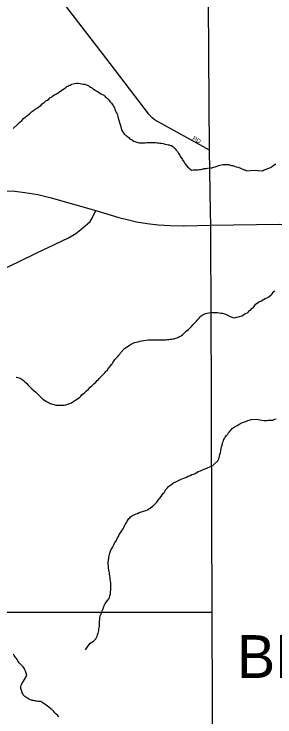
# Model space of a CAD drawing. Extents: x 2010165 to 2382125, y 1060529 to 1407316.
# Drawn here: x 2206176 to 2209222, y 1204883 to 1213095 of the extents above; entities that cross this region are included whole.
import ezdxf

# ---------------------------------------------------------------- set-up
doc = ezdxf.new("R2010")
doc.units = 0
for name, color, linetype in [('GM_X_City_Street', 7, 'Continuous'), ('GM_X_City_Street_Text', 7, 'Continuous'), ('GM_X_Corporation_Text', 7, 'Continuous'), ('GM_X_Minor_River', 7, 'Continuous'), ('GM_X_State_Route', 7, 'Continuous')]:
    doc.layers.add(name, color=color, linetype=linetype)

msp = doc.modelspace()

# ---------------------------------------------------------------- linework, layer by layer
at = {"layer": 'GM_X_City_Street'}
for points in [[(2208456.6, 1211503.7), (2207822.4, 1211855.1), (2207786.6, 1211884.3), (2207748.6, 1211924.5), (2207247.8, 1212584.4), (2206408.8, 1213676.7), (2206379.3, 1213700.3), (2206352.7, 1213718), (2205831, 1213951.2), (2204601.3, 1214502.8), (2204508.6, 1214550.1), (2204421.7, 1214605.1), (2204416.3, 1214608.5)], [(2206573.3, 1210367.5), (2206810.5, 1210481.5), (2206895.8, 1210533.1), (2206975.2, 1210594.6), (2207064.6, 1210672), (2207086.4, 1210709.7), (2207130.1, 1210801)], [(2204477.5, 1203768.7), (2204517.1, 1203815.6), (2205378, 1204812.6), (2205560.9, 1205022), (2205621, 1205118.3), (2205657.1, 1205237.2), (2205848.8, 1206107.4), (2205913.8, 1206390.7), (2205926.1, 1206514.8), (2205923.3, 1206613), (2205534.4, 1208354.5), (2205455.5, 1208700.4), (2205414.2, 1208898.4), (2205410.7, 1208963.9), (2205440, 1209055.1), (2205701.7, 1209548.4), (2205904.8, 1209922.1), (2205958.6, 1210019.5), (2206002.3, 1210073.5), (2206063.1, 1210121.7), (2206236.8, 1210203.6), (2206451.2, 1210308.8), (2206573.3, 1210367.5)], [(2196693.1, 1206074.3), (2200608.2, 1206079.6), (2202550.7, 1206093.1), (2205848.8, 1206107.4), (2208487.9, 1206109.2)]]:
    msp.add_lwpolyline(points, dxfattribs=at)
at = {"layer": 'GM_X_Minor_River'}
for points in [[(2206611.9, 1212125.5), (2206629.6, 1212138), (2206649.3, 1212150.6), (2206671, 1212163.2), (2206690.7, 1212175.8), (2206712.4, 1212190.4), (2206741.9, 1212211.2), (2206757.7, 1212221.7), (2206769.5, 1212230), (2206781.3, 1212238.4), (2206793.1, 1212246.7), (2206804.9, 1212253), (2206816.8, 1212259.4), (2206830.7, 1212265.8), (2206842.6, 1212270.1), (2206852.5, 1212274.3), (2206866.4, 1212278.7), (2206882.3, 1212283.2), (2206906.3, 1212285.8), (2206926.4, 1212286.3), (2206946.5, 1212282.8), (2206964.6, 1212281.3), (2206982.7, 1212277.8), (2207000.9, 1212274.2), (2207019.1, 1212268.7), (2207035.3, 1212263.1), (2207047.5, 1212255.4), (2207057.8, 1212247.6), (2207070, 1212239.9), (2207090.4, 1212228.4), (2207104.7, 1212216.7), (2207169.9, 1212178.3), (2207188.3, 1212164.7), (2207206.6, 1212155.2), (2207218.8, 1212149.4), (2207231.2, 1212137.7), (2207245.6, 1212122), (2207261.9, 1212112.4), (2207274.3, 1212100.7), (2207286.7, 1212087), (2207299.2, 1212069.2), (2207313.6, 1212055.6), (2207321.9, 1212043.7), (2207330.3, 1212031.9), (2207336.6, 1212022), (2207342.8, 1212012.2), (2207347.2, 1211998.2), (2207353.7, 1211982.3), (2207362.2, 1211964.5), (2207368.6, 1211950.6), (2207372.9, 1211938.7), (2207379.2, 1211928.8), (2207383.6, 1211914.9), (2207388, 1211898.9), (2207392.6, 1211876.9), (2207399.2, 1211855), (2207405.9, 1211829.1), (2207414.7, 1211803.2), (2207421.4, 1211777.3), (2207430.3, 1211743.4), (2207440.9, 1211723.6), (2207449.3, 1211709.8), (2207459.6, 1211698), (2207465.9, 1211688.1), (2207480.2, 1211678.5), (2207494.5, 1211668.8), (2207515, 1211651.3), (2207525.3, 1211641.5), (2207535.5, 1211633.8), (2207545.7, 1211628), (2207555.9, 1211622.2), (2207574.3, 1211610.7), (2207620.8, 1211595.8), (2207634.9, 1211592.2), (2207655, 1211590.7), (2207665, 1211591), (2207677.1, 1211591.3), (2207697.1, 1211591.8), (2207707.1, 1211592.1), (2207725.1, 1211594.6), (2207749.1, 1211595.2), (2207769.2, 1211595.7), (2207785.3, 1211594.1), (2207803.3, 1211594.6), (2207827.4, 1211593.2), (2207845.5, 1211591.7), (2207863.6, 1211590.2), (2207879.7, 1211586.6), (2207897.8, 1211585.1), (2207918, 1211581.6), (2207940.2, 1211576.1), (2207960.4, 1211570.6), (2207976.5, 1211567), (2207988.6, 1211565.3), (2208000.8, 1211559.6), (2208012.8, 1211557.9), (2208029.1, 1211548.3), (2208045.6, 1211532.7), (2208056, 1211520.9), (2208070.4, 1211505.3), (2208082.9, 1211487.5)], [(2206166.6, 1211756.4), (2206221.3, 1211810.1), (2206240.9, 1211826.6), (2206266.3, 1211851.4), (2206287.8, 1211874.1), (2206311.3, 1211892.8), (2206334.9, 1211911.4), (2206356.5, 1211930.1), (2206380, 1211950.8), (2206401.6, 1211967.4), (2206423.2, 1211984), (2206448.9, 1211998.8), (2206468.5, 1212013.3), (2206488.2, 1212027.9), (2206505.7, 1212046.4), (2206529.3, 1212063.1), (2206546.9, 1212079.6), (2206564.7, 1212090.1), (2206580.4, 1212102.6), (2206594.1, 1212115), (2206611.9, 1212125.5)], [(2208082.9, 1211487.5), (2208095.6, 1211465.8), (2208110.1, 1211446.1), (2208120.6, 1211428.3), (2208133.2, 1211406.5), (2208141.6, 1211394.7), (2208147.9, 1211382.8), (2208160.5, 1211363.1), (2208170.9, 1211347.3), (2208185.5, 1211329.6), (2208202, 1211309.9), (2208218.5, 1211294.3), (2208232.8, 1211282.7), (2208249.1, 1211273.1), (2208267.2, 1211273.5), (2208287.2, 1211274), (2208307.2, 1211276.6), (2208323.2, 1211277), (2208339.3, 1211277.4), (2208353.2, 1211279.8), (2208367.2, 1211282.2), (2208377.2, 1211284.4), (2208393.1, 1211288.9), (2208407.1, 1211291.2), (2208417.1, 1211291.5), (2208435.1, 1211294), (2208453, 1211296.5), (2208471.1, 1211296.9), (2208485.1, 1211299.3), (2208497, 1211301.6), (2208508.9, 1211306), (2208524.9, 1211310.4), (2208536.8, 1211314.7), (2208546.7, 1211319), (2208562.6, 1211325.4), (2208576.5, 1211329.8), (2208596.4, 1211334.3), (2208612.4, 1211336.8), (2208628.4, 1211337.2), (2208646.5, 1211337.7), (2208668.5, 1211338.3), (2208682.6, 1211336.6), (2208700.8, 1211331.1), (2208714.9, 1211327.4), (2208731, 1211323.8), (2208749.2, 1211318.3), (2208769.5, 1211310.8), (2208791.7, 1211305.3), (2208810, 1211297.8), (2208828.2, 1211290.2), (2208846.5, 1211282.7), (2208860.6, 1211277), (2208870.8, 1211273.3), (2208895.1, 1211261.9), (2208974.2, 1211269.9)], [(2208974.2, 1211271.2), (2209075.2, 1211261.8), (2209089.1, 1211272), (2209150.9, 1211294.9), (2209170.8, 1211303.1), (2209192.7, 1211317.5), (2209214.5, 1211331.8), (2209230.4, 1211346.1)], [(2209221.8, 1209862.3), (2209207.9, 1209850.1), (2209194.1, 1209837.9), (2209186.2, 1209827.8), (2209176.4, 1209811.6), (2209164.4, 1209805.4), (2209152.6, 1209793.2), (2209140.7, 1209785), (2209108.8, 1209768.5), (2209088.9, 1209758.2), (2209079, 1209752.1), (2209069, 1209745.9), (2209055.1, 1209737.7), (2209043.2, 1209731.6), (2209031.3, 1209723.4), (2209029.3, 1209723.3), (2208989.5, 1209699.6)], [(2208079.5, 1209313.2), (2208095.4, 1209319.7), (2208109.3, 1209326.1), (2208125.1, 1209334.5), (2208140.8, 1209347), (2208160.3, 1209365.5), (2208185.7, 1209390.3), (2208213.3, 1209411.1), (2208230.9, 1209427.6), (2208246.4, 1209444.1), (2208267.9, 1209466.7), (2208279.5, 1209481.1), (2208293.2, 1209493.5), (2208304.9, 1209505.8), (2208314.6, 1209518.1), (2208326.3, 1209530.5), (2208338, 1209542.8), (2208349.7, 1209557.2), (2208361.4, 1209567.6), (2208371.2, 1209577.8), (2208412.8, 1209595), (2208430.7, 1209599.5), (2208448.7, 1209604), (2208468.7, 1209606.5), (2208486.7, 1209607), (2208504.7, 1209607.4), (2208526.8, 1209608), (2208548.9, 1209606.6), (2208569, 1209605.1), (2208589.1, 1209601.6), (2208609.2, 1209600.1), (2208631.5, 1209592.7), (2208645.6, 1209587.1), (2208659.9, 1209579.4), (2208682.2, 1209569.9), (2208706.6, 1209556.5), (2208730.8, 1209551.1), (2208751, 1209547.7), (2208774.9, 1209552.3), (2208806.8, 1209561.2), (2208834.6, 1209569.9), (2208856.4, 1209580.6), (2208876, 1209595.1), (2208899.8, 1209605.8), (2208913.6, 1209616.2), (2208925.2, 1209630.5), (2208935.1, 1209636.8), (2208950.7, 1209653.3), (2208966.4, 1209663.7), (2208989.5, 1209699.6)], [(2206199, 1208854.3), (2206205, 1208852.5), (2206219.2, 1208848.8), (2206235.4, 1208843.2), (2206251.6, 1208835.7), (2206265.9, 1208828), (2206286.3, 1208814.5), (2206302.7, 1208798.8), (2206321.3, 1208781.3), (2206341.9, 1208759.7), (2206364.6, 1208736.2), (2206385.2, 1208714.7), (2206407.8, 1208695.2), (2206428.4, 1208675.7), (2206448.9, 1208658.1), (2206467.5, 1208638.6), (2206490.1, 1208619.1), (2206512.8, 1208595.6), (2206543.4, 1208576.3), (2206563.8, 1208562.8), (2206584.1, 1208553.3), (2206598.4, 1208545.6), (2206612.5, 1208542), (2206626.7, 1208536.3), (2206644.8, 1208532.8), (2206663, 1208527.3), (2206683.2, 1208523.8), (2206761.3, 1208525.8), (2206781.3, 1208530.4), (2206805.1, 1208537), (2206827, 1208545.6), (2206844.8, 1208554.1), (2206862.5, 1208564.6), (2206884.2, 1208579.2), (2206927.6, 1208606.5), (2206943.3, 1208618.9), (2206957, 1208629.3), (2206972.5, 1208649.8), (2206998.1, 1208668.6), (2207021.5, 1208693.2), (2207045, 1208713.9), (2207066.5, 1208734.6), (2207086, 1208753.2), (2207107.5, 1208773.8), (2207129, 1208794.4), (2207146.6, 1208813), (2207162.2, 1208827.4), (2207173.9, 1208841.8), (2207183.6, 1208854.1), (2207193.4, 1208862.4), (2207207, 1208876.8), (2207218.7, 1208889.1), (2207234.4, 1208903.6), (2207248, 1208918), (2207255.8, 1208928.3), (2207265.6, 1208936.5), (2207271.3, 1208946.7), (2207282.9, 1208963.1), (2207294.6, 1208975.4), (2207304.3, 1208987.7), (2207312, 1209000), (2207319.7, 1209010.2), (2207329.4, 1209022.5), (2207341, 1209038.9), (2207354.5, 1209057.3), (2207370.1, 1209075.8), (2207387.6, 1209094.3), (2207399.2, 1209110.7), (2207410.9, 1209123), (2207420.6, 1209135.3), (2207465.3, 1209186.7), (2207486.9, 1209203.3), (2207506.7, 1209215.9), (2207522.4, 1209226.3), (2207536.2, 1209234.7), (2207550, 1209243.1), (2207567.9, 1209249.6), (2207583.8, 1209256.1), (2207601.7, 1209262.5), (2207625.6, 1209267.2), (2207643.5, 1209271.7), (2207665.5, 1209276.3), (2207691.4, 1209281), (2207717.4, 1209283.6), (2207741.3, 1209288.3), (2207767.4, 1209289), (2207795.4, 1209289.7), (2207831.6, 1209288.6), (2207857.6, 1209289.3), (2207881.7, 1209288), (2207903.7, 1209288.5), (2207925.8, 1209289.1), (2207947.8, 1209289.7), (2207967.8, 1209292.2), (2207983.8, 1209292.6), (2207999.8, 1209295.1), (2208013.8, 1209295.4), (2208029.8, 1209299.9), (2208043.7, 1209302.2), (2208063.7, 1209306.8), (2208079.5, 1209313.2)], [(2207788, 1207340.3), (2207807.6, 1207356.8), (2207825.2, 1207373.4), (2207842.7, 1207393.9), (2207860.2, 1207414.4), (2207877.6, 1207439), (2207893.1, 1207457.4), (2207906.6, 1207477.9), (2207920.2, 1207496.3), (2207933.8, 1207510.7), (2207941.4, 1207525), (2207949, 1207541.2), (2207960.8, 1207551.6), (2207968.5, 1207561.8), (2207978.2, 1207574.1), (2207995.9, 1207588.6), (2208005.7, 1207596.9), (2208021.5, 1207605.4), (2208039.1, 1207619.9), (2208062.9, 1207630.5), (2208086.6, 1207643.2), (2208112.4, 1207653.9), (2208128.3, 1207660.4), (2208148.1, 1207668.9), (2208167.9, 1207677.4), (2208187.7, 1207686), (2208209.6, 1207694.6), (2208231.4, 1207703.2), (2208253.2, 1207713.8), (2208275, 1207720.4), (2208290.9, 1207728.9), (2208308.7, 1207737.3), (2208326.4, 1207749.9), (2208352.2, 1207758.6), (2208368, 1207767), (2208385.9, 1207773.5), (2208413.6, 1207786.3), (2208427.6, 1207790.7), (2208443.4, 1207797.1), (2208461.2, 1207805.6), (2208481.1, 1207814.1), (2208496.9, 1207822.6), (2208512.6, 1207835.1), (2208553.6, 1207874.3), (2208559.4, 1207884.5), (2208565, 1207898.7), (2208570.6, 1207912.9), (2208576.2, 1207929.1), (2208579.7, 1207949.2), (2208585.1, 1207969.4), (2208588.5, 1207991.6), (2208594, 1208013.8), (2208597.3, 1208040), (2208604.7, 1208060.3), (2208608.3, 1208076.4), (2208613.9, 1208092.7), (2208619.5, 1208108.9), (2208625.1, 1208123.1), (2208632.7, 1208137.3), (2208642.4, 1208151.6), (2208657.9, 1208172.1), (2208667.6, 1208184.4), (2208677.2, 1208196.7), (2208690.8, 1208215.1), (2208700.5, 1208225.4), (2208710.2, 1208237.7), (2208723.9, 1208252.1), (2208735.7, 1208260.5), (2208759.3, 1208277.1), (2208779.1, 1208287.7), (2208800.8, 1208300.3), (2208824.4, 1208315), (2208854.2, 1208325.8), (2208870.1, 1208332.2), (2208880, 1208336.5), (2208895.9, 1208343), (2208905.8, 1208347.2), (2208919.7, 1208351.6), (2208933.6, 1208356), (2208943.6, 1208358.3), (2209002.6, 1208363.9)], [(2209002.6, 1208363.9), (2209091.4, 1208345), (2209109.5, 1208345.2), (2209127.5, 1208347.4), (2209141.5, 1208349.6), (2209159.5, 1208349.8), (2209195.5, 1208352.3), (2209219.5, 1208360.6), (2209237.4, 1208366.9)], [(2207009.2, 1205665.6), (2207032.2, 1205702.4), (2207065.1, 1205745.4), (2207102.6, 1205768.5), (2207120.3, 1205783), (2207130, 1205795.3), (2207137.6, 1205809.5), (2207145.2, 1205825.8), (2207150.7, 1205844), (2207158.2, 1205862.3), (2207161.8, 1205878.4), (2207165.4, 1205894.6), (2207167, 1205908.7), (2207170.6, 1205924.8), (2207172, 1205944.9), (2207173.6, 1205961.1), (2207173.2, 1205977.1), (2207172.9, 1205989.1), (2207174.5, 1206003.2), (2207176, 1206021.3), (2207177.5, 1206041.4), (2207182.9, 1206063.7), (2207192.3, 1206086), (2207199.8, 1206106.3), (2207205.3, 1206122.5), (2207211, 1206136.7), (2207214.7, 1206148.8), (2207220.3, 1206163), (2207227.8, 1206183.3), (2207241.1, 1206207.7), (2207256.6, 1206228.2), (2207270.2, 1206246.6), (2207281.7, 1206265), (2207289.3, 1206279.3), (2207294.9, 1206297.5), (2207300.3, 1206319.7), (2207303.6, 1206343.9), (2207305, 1206366), (2207304.4, 1206388.1), (2207305.7, 1206416.2), (2207304.9, 1206446.3), (2207302.1, 1206474.3), (2207299.7, 1206490.3), (2207297.1, 1206510.3), (2207294.6, 1206530.3), (2207292, 1206550.3), (2207289.5, 1206568.3), (2207287.1, 1206582.3), (2207280.1, 1206620.3), (2207277.8, 1206632.3), (2207277.4, 1206648.3), (2207274.9, 1206664.3), (2207274.5, 1206680.4), (2207276, 1206698.5), (2207277.7, 1206710.6), (2207277.3, 1206722.6), (2207281, 1206734.8), (2207282.7, 1206746.8), (2207286.2, 1206767), (2207289.8, 1206779.1), (2207293.4, 1206795.3), (2207297.1, 1206807.4), (2207300.8, 1206819.6), (2207306.5, 1206831.8), (2207310.2, 1206841.9), (2207316, 1206852.1), (2207323.6, 1206864.3), (2207331.3, 1206878.6), (2207340.9, 1206892.9), (2207348.4, 1206913.2), (2207360, 1206927.5), (2207367.7, 1206941.8), (2207375.2, 1206958.1), (2207384.8, 1206974.4), (2207394.4, 1206992.7), (2207403.8, 1207013), (2207417.3, 1207033.4), (2207430.8, 1207053.9), (2207442.4, 1207070.2), (2207450.1, 1207080.5), (2207457.8, 1207094.7), (2207467.3, 1207115), (2207474.8, 1207131.3), (2207484.4, 1207147.6), (2207492.1, 1207159.9), (2207497.8, 1207170.1), (2207503.5, 1207182.2), (2207517, 1207202.7), (2207526.8, 1207210.9), (2207536.6, 1207219.2), (2207558.2, 1207237.9), (2207574, 1207244.3), (2207586, 1207248.6), (2207599.8, 1207255), (2207615.7, 1207261.5), (2207637.5, 1207270.1), (2207713, 1207296.1), (2207732.8, 1207304.7), (2207748.6, 1207313.1), (2207764.4, 1207323.6), (2207788, 1207340.3)], [(2206699.4, 1204882.6), (2206684.9, 1204902.3), (2206664.4, 1204917.8), (2206652, 1204931.5), (2206639.5, 1204947.3), (2206629.2, 1204959), (2206618.9, 1204968.8), (2206606.7, 1204976.5), (2206596.4, 1204986.3), (2206582, 1204997.9), (2206567.7, 1205009.6), (2206551.4, 1205019.2), (2206535, 1205030.8), (2206516.7, 1205042.4), (2206502.3, 1205054.1), (2206488, 1205063.7), (2206478, 1205063.5), (2206465.9, 1205065.2), (2206455.9, 1205064.9), (2206441.8, 1205066.6), (2206429.7, 1205068.2), (2206417.6, 1205071.9), (2206401.5, 1205075.5), (2206389.4, 1205077.2), (2206379.3, 1205081), (2206369.1, 1205084.7), (2206359, 1205088.4), (2206348.9, 1205092.2), (2206338.6, 1205100), (2206326.4, 1205107.7), (2206314.2, 1205115.4), (2206301.9, 1205123.1), (2206283.3, 1205142.7), (2206277.1, 1205152.6), (2206272.7, 1205164.5), (2206266.2, 1205184.4), (2206259.7, 1205202.3), (2206255.3, 1205216.2), (2206255, 1205226.3), (2206256.6, 1205240.3), (2206260.3, 1205254.5), (2206265.9, 1205268.7), (2206298.5, 1205321.8), (2206304.2, 1205333.9), (2206310, 1205344.1), (2206317.7, 1205354.4), (2206323.4, 1205366.6), (2206321.1, 1205378.6), (2206320.8, 1205388.6), (2206314.4, 1205404.5), (2206310, 1205418.4), (2206303.6, 1205432.3), (2206297.2, 1205446.2), (2206290.9, 1205458.1), (2206282.6, 1205467.9), (2206270.2, 1205481.6), (2206257.9, 1205491.3), (2206245.5, 1205505.1), (2206235.1, 1205516.8), (2206228.8, 1205526.7), (2206220.4, 1205540.5), (2206212.1, 1205552.4), (2206203.8, 1205564.2), (2206197.5, 1205574.1), (2206187, 1205589.8), (2206176.7, 1205601.6), (2206170.3, 1205615.5)]]:
    msp.add_lwpolyline(points, dxfattribs=at)
at = {"layer": 'GM_X_State_Route'}
for points in [[(2208449.9, 1212623.7), (2208431.1, 1215769.2), (2208422.9, 1216772.2)], [(2208469.1, 1210785.9), (2208456.6, 1211503.7), (2208449.9, 1212623.7)], [(2204655.4, 1210525.8), (2204662.3, 1210529.9), (2204938.1, 1210699.4), (2205166.1, 1210827.8), (2205315.5, 1210895.9), (2205443.9, 1210943.1), (2205606.4, 1210987.7), (2205761, 1211013.9), (2205876.3, 1211027), (2206036.2, 1211029.6), (2206185.5, 1211024.4), (2206300.9, 1211011.3), (2206452.9, 1210985), (2206611, 1210946.8), (2207130.1, 1210801), (2207400, 1210719.7), (2207511.2, 1210691.9), (2207604.5, 1210668.1), (2207729.5, 1210648.2), (2207859.5, 1210633.3), (2207998.5, 1210625.4), (2208153.6, 1210621.6)], [(2208471.9, 1210628.4), (2209271.8, 1210639.3), (2209375, 1210636.3), (2209462.4, 1210642.2), (2209582.5, 1210653.2), (2209648, 1210663.1), (2209734.3, 1210682.9), (2209832.4, 1210713.2), (2209876.3, 1210727.6), (2209910, 1210740.5), (2210016.2, 1210796.1), (2210115.5, 1210849.7), (2210164.2, 1210876.8)], [(2208476.5, 1209461.3), (2208471.9, 1210628.4), (2208469.1, 1210785.9)], [(2208153.6, 1210621.6), (2208161.3, 1210621.4), (2208471.9, 1210628.4)], [(2208479.2, 1208771.6), (2208476.5, 1209461.3)], [(2208507.5, 1199487.9), (2208498.3, 1202183.8), (2208496.5, 1203898.9), (2208487.9, 1206109.2), (2208480.8, 1208362.2), (2208479.2, 1208771.6)]]:
    msp.add_lwpolyline(points, dxfattribs=at)

# ---------------------------------------------------------------- texts
at = {"layer": 'GM_X_City_Street_Text'}
msp.add_text('RD', height=50, rotation=330.64355, dxfattribs=at).set_placement((2208252.9, 1211628.1))
at = {"layer": 'GM_X_Corporation_Text'}
msp.add_text('BRECKSVILLE', height=500, rotation=0.00001, dxfattribs=at).set_placement((2208778.8, 1205338.7))

doc.saveas('drawing.dxf')
